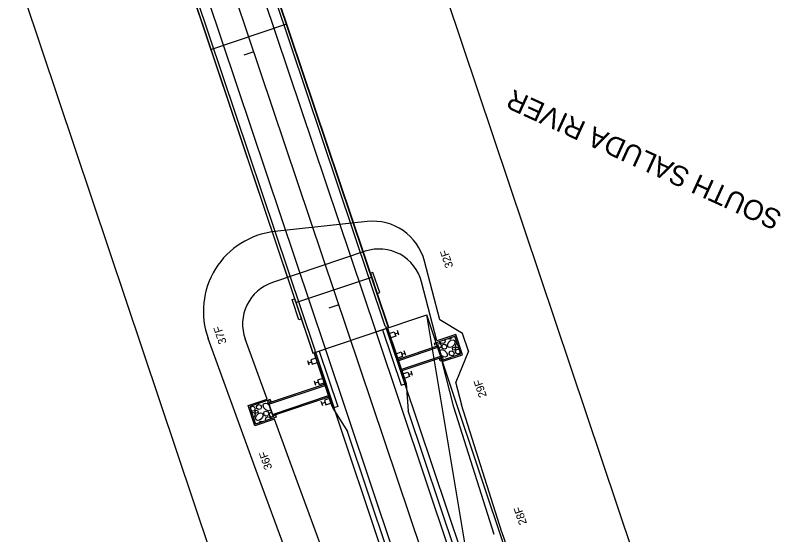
# Model space of a CAD drawing. Extents: x 1528853 to 1624411, y 1119753 to 1162242.
# Drawn here: x 1529554.1 to 1529845.6, y 1160111 to 1160305.3 of the extents above; entities that cross this region are included whole.
import ezdxf

# ---------------------------------------------------------------- set-up
doc = ezdxf.new("R2010")
doc.units = 0
for name, color, linetype in [('BR_CONCRETE', 7, 'Continuous'), ('BR_PROPOSED_TRAVELWAY', 7, 'Continuous'), ('Drainage-Trench', 7, 'Continuous'), ('RD_HC_Cl', 7, 'Continuous'), ('RD_HC_Data', 7, 'Continuous'), ('RD_HC_Data_Tic', 7, 'Continuous'), ('RD_PD_BOC', 7, 'Continuous'), ('RD_PD_CstnLmt', 7, 'Continuous'), ('RD_PD_CstnLmt_TX', 7, 'Continuous'), ('RD_PD_DR_ErosCtrl', 7, 'Continuous'), ('RD_PD_DR_Inlet', 7, 'Continuous'), ('RD_PD_Final_TrvlWay', 7, 'Continuous'), ('RD_PD_GR', 7, 'Continuous'), ('RD_PD_PaveDit', 7, 'Continuous'), ('RD_PD_PaveShd', 7, 'Continuous'), ('RD_PD_RW', 7, 'Continuous'), ('RD_Sketch8', 7, 'Continuous')]:
    doc.layers.add(name, color=color, linetype=linetype)

# ---------------------------------------------------------------- blocks, each defined once
blk = doc.blocks.new('Guardrail_MTBBC2_Transition')
at = {"layer": 'RD_PD_GR'}
for p, q in [((3.875, 3.75), (2.125, 3.75)), ((3, 2.5), (3, 3.75)), ((11.875, 3.75), (10.125, 3.75)), ((11, 2.5), (11, 3.75)), ((19.875, 3.75), (18.125, 3.75)), ((19, 2.5), (19, 3.75)), ((0, 0.5), (0, 0)), ((21.25, 0.5), (0, 0.5)), ((0, 0), (21.25, 0)), ((2.125, 0.5), (2.125, 2.5)), ((2.125, 2.5), (3.875, 2.5)), ((3.875, 0.5), (2.125, 0.5)), ((3.875, 2.5), (3.875, 0.5)), ((10.125, 0.5), (10.125, 2.5)), ((10.125, 2.5), (11.875, 2.5)), ((11.875, 0.5), (10.125, 0.5)), ((11.875, 2.5), (11.875, 0.5)), ((15, 0.5), (15, 0)), ((18.125, 0.5), (18.125, 2.5)), ((18.125, 2.5), (19.875, 2.5)), ((19.875, 0.5), (18.125, 0.5)), ((19.875, 2.5), (19.875, 0.5)), ((21.25, 0), (21.25, 0.5))]:
    blk.add_line(p, q, dxfattribs=at)

msp = doc.modelspace()

# ---------------------------------------------------------------- linework, layer by layer
at = {"layer": 'BR_CONCRETE'}
for p, q in [((1529692.58, 1160189.08), (1529632.72, 1160367.29)), ((1529693.85, 1160188.45), (1529633.35, 1160368.56)), ((1529693.93, 1160188.48), (1529633.43, 1160368.58)), ((1529604.99, 1160359.03), (1529665.49, 1160178.92)), ((1529665.57, 1160178.95), (1529605.07, 1160359.06)), ((1529666.2, 1160180.22), (1529606.34, 1160358.43)), ((1529627.28, 1160292.68), (1529655.72, 1160302.23)), ((1529659.12, 1160197.88), (1529687.56, 1160207.43)), ((1529692.58, 1160189.08), (1529693.14, 1160188.21)), ((1529665.49, 1160178.92), (1529693.93, 1160188.48)), ((1529666.2, 1160180.22), (1529666.28, 1160179.19))]:
    msp.add_line(p, q, dxfattribs=at)
for points in [[(1529688.03, 1160209.17), (1529687.08, 1160208.86), (1529689.63, 1160201.27), (1529690.58, 1160201.59)], [(1529657.7, 1160198.98), (1529658.65, 1160199.3), (1529661.19, 1160191.72), (1529660.24, 1160191.4)]]:
    msp.add_lwpolyline(points, close=True, dxfattribs=at)
at = {"layer": 'BR_PROPOSED_TRAVELWAY'}
for p, q in [((1529689.19, 1160186.88), (1529628.69, 1160366.99)), ((1529670.23, 1160180.51), (1529609.73, 1160360.62))]:
    msp.add_line(p, q, dxfattribs=at)
at = {"layer": 'Drainage-Trench'}
for p, q in [((1529711.03, 1160182.71), (1529718.73, 1160185.29)), ((1529720.96, 1160178.66), (1529718.73, 1160185.29)), ((1529711.35, 1160181.76), (1529711.03, 1160182.71)), ((1529713.89, 1160177.34), (1529712.3, 1160182.08)), ((1529713.26, 1160176.07), (1529720.96, 1160178.66)), ((1529713.26, 1160176.07), (1529712.94, 1160177.02)), ((1529649.54, 1160161.52), (1529641.84, 1160158.93)), ((1529648.91, 1160160.25), (1529650.5, 1160155.51)), ((1529649.54, 1160161.52), (1529649.85, 1160160.57)), ((1529641.84, 1160158.93), (1529644.07, 1160152.3)), ((1529651.76, 1160154.88), (1529644.07, 1160152.3)), ((1529651.45, 1160155.83), (1529651.76, 1160154.88))]:
    msp.add_line(p, q, dxfattribs=at)
at = {"layer": 'RD_HC_Cl'}
msp.add_line((1529913.5, 1159487.74), (1529500.12, 1160718.34), dxfattribs=at)
at = {"layer": 'RD_HC_Data_Tic'}
for p, q in [((1529643.41, 1160291.76), (1529639.62, 1160290.49)), ((1529675.25, 1160196.97), (1529671.46, 1160195.7))]:
    msp.add_line(p, q, dxfattribs=at)
at = {"layer": 'RD_PD_BOC'}
for p, q in [((1529691.56, 1160187.68), (1529698.54, 1160166.9)), ((1529693.46, 1160188.32), (1529700.43, 1160167.54)), ((1529665.97, 1160179.08), (1529672.94, 1160158.31)), ((1529667.86, 1160179.72), (1529674.84, 1160158.94)), ((1529698.54, 1160166.9), (1529700.43, 1160167.54)), ((1529674.84, 1160158.94), (1529672.94, 1160158.31))]:
    msp.add_line(p, q, dxfattribs=at)
at = {"layer": 'RD_PD_CstnLmt'}
for p, q in [((1529685.13, 1160217.06), (1529650.36, 1160205.38)), ((1529711.96, 1160183.54), (1529706.23, 1160205.63)), ((1529719.05, 1160185.92), (1529711.96, 1160183.54)), ((1529721.59, 1160178.34), (1529719.05, 1160185.92)), ((1529648.38, 1160161.66), (1529640.17, 1160184.23)), ((1529713.97, 1160175.78), (1529721.59, 1160178.34)), ((1529718.39, 1160158.72), (1529713.97, 1160175.78)), ((1529641.21, 1160159.25), (1529648.38, 1160161.66)), ((1529643.75, 1160151.67), (1529641.21, 1160159.25)), ((1529733.43, 1160111.02), (1529718.39, 1160158.72)), ((1529651.12, 1160154.14), (1529643.75, 1160151.67)), ((1529656.96, 1160138.08), (1529651.12, 1160154.14)), ((1529674.28, 1160091.15), (1529656.96, 1160138.08))]:
    msp.add_line(p, q, dxfattribs=at)
for centre, start, end in [((1529690.36, 1160201.52), 14.533, 108.568), ((1529655.58, 1160189.83), 108.568, 199.9899)]:
    msp.add_arc(centre, 16.4, start, end, dxfattribs=at)
at = {"layer": 'RD_PD_DR_ErosCtrl'}
for p, q in [((1529685.8, 1160228.21), (1529651.23, 1160224.44)), ((1529713.03, 1160191.34), (1529707.33, 1160213.35)), ((1529721.58, 1160186.25), (1529713.03, 1160191.34)), ((1529723.8, 1160179.61), (1529721.58, 1160186.25)), ((1529644.75, 1160133.61), (1529626.29, 1160184.36)), ((1529723.8, 1160179.61), (1529719.09, 1160167.99)), ((1529721.3, 1160159.47), (1529719.09, 1160167.99)), ((1529736.3, 1160111.92), (1529721.25, 1160159.62)), ((1529661.93, 1160087.08), (1529644.75, 1160133.61)), ((1529753.24, 1160065), (1529736.28, 1160111.98))]:
    msp.add_line(p, q, dxfattribs=at)
for centre, radius, start, end in [((1529687.97, 1160208.33), 20, 14.533, 96.2338), ((1529654.48, 1160194.61), 30, 96.2338, 199.9899)]:
    msp.add_arc(centre, radius, start, end, dxfattribs=at)
at = {"layer": 'RD_PD_DR_Inlet'}
for p, q in [((1529712.46, 1160181.6), (1529697.41, 1160176.55)), ((1529712.62, 1160181.13), (1529697.57, 1160176.07)), ((1529712.46, 1160181.6), (1529713.89, 1160177.34)), ((1529713.73, 1160177.81), (1529698.68, 1160172.75)), ((1529713.89, 1160177.34), (1529698.84, 1160172.28)), ((1529648.91, 1160160.25), (1529669.92, 1160167.31)), ((1529649.07, 1160159.78), (1529670.08, 1160166.84)), ((1529650.34, 1160155.99), (1529671.35, 1160163.05)), ((1529650.5, 1160155.51), (1529671.51, 1160162.57)), ((1529650.5, 1160155.51), (1529648.91, 1160160.25))]:
    msp.add_line(p, q, dxfattribs=at)
at = {"layer": 'RD_PD_Final_TrvlWay'}
for p, q in [((1529922.97, 1159490.92), (1529689.19, 1160186.88)), ((1529904.02, 1159484.55), (1529670.23, 1160180.51))]:
    msp.add_line(p, q, dxfattribs=at)
at = {"layer": 'RD_PD_GR'}
for p, q in [((1529699.75, 1160168.01), (1529727.61, 1160085.07)), ((1529734.82, 1159975.67), (1529673.21, 1160159.1))]:
    msp.add_line(p, q, dxfattribs=at)
at = {"layer": 'RD_PD_PaveDit'}
for p, q in [((1529712.95, 1160182.99), (1529712.72, 1160183.27)), ((1529716.84, 1160184.17), (1529716.08, 1160184.4)), ((1529712.82, 1160180.69), (1529712.76, 1160180.71)), ((1529713.86, 1160177.89), (1529713.6, 1160178.2)), ((1529648.94, 1160159.7), (1529649.2, 1160159.39)), ((1529649.97, 1160156.89), (1529650.04, 1160156.88)), ((1529649.85, 1160154.6), (1529650.08, 1160154.32)), ((1529645.96, 1160153.42), (1529646.72, 1160153.19))]:
    msp.add_line(p, q, dxfattribs=at)
for points in [[(1529714.82, 1160183.98), (1529715.03, 1160183.38), (1529714.85, 1160182.78), (1529714.18, 1160182.5), (1529713.43, 1160182.69), (1529712.92, 1160183.02)], [(1529716.46, 1160183.09), (1529717.23, 1160183.74), (1529718.08, 1160183.95), (1529718.59, 1160183.71), (1529718.8, 1160183.03), (1529718.46, 1160182.08), (1529717.7, 1160181.31), (1529716.84, 1160181.01), (1529716.24, 1160181.19), (1529715.97, 1160181.86), (1529716.15, 1160182.61), (1529716.48, 1160183.12)], [(1529717.6, 1160184.91), (1529717.4, 1160184.49), (1529716.84, 1160184.17)], [(1529718.92, 1160184.72), (1529718.72, 1160184.96), (1529718.65, 1160185.26)], [(1529711.79, 1160181.91), (1529712.06, 1160182.41), (1529712.85, 1160182.59), (1529713.4, 1160182.25), (1529713.6, 1160181.48), (1529713.38, 1160181.01), (1529712.82, 1160180.69)], [(1529713.1, 1160179.71), (1529713.24, 1160180.03), (1529713.91, 1160180.24), (1529714.87, 1160179.9), (1529715.64, 1160179.14), (1529715.94, 1160178.28), (1529715.76, 1160177.68), (1529715.09, 1160177.4), (1529714.34, 1160177.59), (1529713.83, 1160177.92)], [(1529714.93, 1160180.4), (1529714.08, 1160180.65), (1529713.78, 1160181.4), (1529714.16, 1160182.11), (1529714.95, 1160182.29), (1529715.5, 1160181.95), (1529715.7, 1160181.18), (1529715.48, 1160180.71), (1529714.93, 1160180.4)], [(1529718.5, 1160180.02), (1529718, 1160180.17), (1529717.82, 1160180.62), (1529718.04, 1160181.05), (1529718.52, 1160181.15), (1529718.85, 1160180.95), (1529718.97, 1160180.49), (1529718.83, 1160180.21), (1529718.5, 1160180.02)], [(1529720.06, 1160180.81), (1529719.22, 1160181.06), (1529718.92, 1160181.81), (1529719.29, 1160182.53), (1529719.63, 1160182.6)], [(1529720.07, 1160178.57), (1529719.23, 1160178.82), (1529718.93, 1160179.56), (1529719.3, 1160180.28), (1529720.09, 1160180.46), (1529720.42, 1160180.26)], [(1529720.21, 1160180.9), (1529720.06, 1160180.81)], [(1529713.76, 1160176.48), (1529713.25, 1160176.63), (1529713.08, 1160177.06)], [(1529713.81, 1160177.59), (1529714.1, 1160177.41), (1529714.22, 1160176.95), (1529714.09, 1160176.67), (1529713.75, 1160176.48)], [(1529717.66, 1160177.91), (1529716.82, 1160178.16), (1529716.52, 1160178.91), (1529716.89, 1160179.62), (1529717.69, 1160179.8), (1529718.24, 1160179.46), (1529718.44, 1160178.69), (1529718.21, 1160178.22), (1529717.66, 1160177.91)], [(1529720.77, 1160179.21), (1529720.62, 1160178.88), (1529720.07, 1160178.57)], [(1529645.14, 1160159.68), (1529645.98, 1160159.43), (1529646.28, 1160158.68), (1529645.91, 1160157.97), (1529645.11, 1160157.79), (1529644.56, 1160158.13), (1529644.36, 1160158.9), (1529644.59, 1160159.37), (1529645.14, 1160159.68)], [(1529649.7, 1160157.88), (1529649.56, 1160157.56), (1529648.89, 1160157.35), (1529647.93, 1160157.69), (1529647.16, 1160158.45), (1529646.86, 1160159.31), (1529647.04, 1160159.91), (1529647.71, 1160160.19), (1529648.46, 1160160), (1529648.97, 1160159.67)], [(1529648.99, 1160160), (1529648.7, 1160160.18), (1529648.58, 1160160.64), (1529648.71, 1160160.92), (1529649.04, 1160161.11)], [(1529649.04, 1160161.11), (1529649.55, 1160160.96), (1529649.72, 1160160.53)], [(1529642.02, 1160158.38), (1529642.18, 1160158.71), (1529642.73, 1160159.02)], [(1529642.73, 1160159.02), (1529643.57, 1160158.77), (1529643.87, 1160158.02), (1529643.5, 1160157.31), (1529642.7, 1160157.13), (1529642.38, 1160157.33)], [(1529642.59, 1160156.69), (1529642.74, 1160156.78)], [(1529642.74, 1160156.78), (1529643.58, 1160156.53), (1529643.88, 1160155.78), (1529643.5, 1160155.06), (1529643.17, 1160154.99)], [(1529644.3, 1160157.57), (1529644.8, 1160157.42), (1529644.98, 1160156.97), (1529644.76, 1160156.54), (1529644.28, 1160156.43), (1529643.95, 1160156.64), (1529643.83, 1160157.1), (1529643.97, 1160157.38), (1529644.3, 1160157.57)], [(1529647.87, 1160157.19), (1529648.71, 1160156.94), (1529649.01, 1160156.19), (1529648.64, 1160155.48), (1529647.85, 1160155.29), (1529647.3, 1160155.63), (1529647.1, 1160156.41), (1529647.32, 1160156.88), (1529647.87, 1160157.19)], [(1529651, 1160155.68), (1529650.74, 1160155.18), (1529649.95, 1160155), (1529649.4, 1160155.34), (1529649.2, 1160156.11), (1529649.42, 1160156.58), (1529649.97, 1160156.89)], [(1529646.34, 1160154.5), (1529645.57, 1160153.85), (1529644.72, 1160153.64), (1529644.21, 1160153.88), (1529644, 1160154.55), (1529644.33, 1160155.51), (1529645.1, 1160156.28), (1529645.95, 1160156.58), (1529646.56, 1160156.4), (1529646.83, 1160155.73), (1529646.65, 1160154.98), (1529646.32, 1160154.47)], [(1529647.98, 1160153.61), (1529647.77, 1160154.21), (1529647.95, 1160154.81), (1529648.62, 1160155.09), (1529649.37, 1160154.9), (1529649.88, 1160154.57)], [(1529643.88, 1160152.87), (1529644.08, 1160152.63), (1529644.15, 1160152.33)], [(1529645.2, 1160152.68), (1529645.4, 1160153.1), (1529645.96, 1160153.42)]]:
    msp.add_lwpolyline(points, dxfattribs=at)
at = {"layer": 'RD_PD_PaveShd'}
for p, q in [((1529700.43, 1160167.54), (1529701.25, 1160157.28)), ((1529672.94, 1160158.31), (1529678.5, 1160149.61)), ((1529754.8, 1159997.85), (1529701.25, 1160157.28)), ((1529732.05, 1159990.21), (1529678.5, 1160149.61))]:
    msp.add_line(p, q, dxfattribs=at)
at = {"layer": 'RD_PD_RW'}
for p, q in [((1529881.68, 1159817.98), (1529571.21, 1160742.22)), ((1529715.61, 1159841.31), (1529429.02, 1160694.46))]:
    msp.add_line(p, q, dxfattribs=at)
at = {"layer": 'RD_Sketch8'}
for p in [(1529689.19, 1160186.88), (1529747.95, 1160074.76), (1529728.99, 1160068.39)]:
    msp.add_line(p, (1529708.15, 1160193.25), dxfattribs=at)

# ---------------------------------------------------------------- block references
at = {"layer": 'RD_PD_BOC', "rotation": -71.4319942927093}
msp.add_blockref('Guardrail_MTBBC2_Transition', (1529692.98, 1160188.16), dxfattribs=at)
at = {"layer": 'RD_PD_BOC', "yscale": -0.9999999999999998, "rotation": -71.43199429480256}
msp.add_blockref('Guardrail_MTBBC2_Transition', (1529666.44, 1160179.24), dxfattribs=at)

# ---------------------------------------------------------------- texts
at = {"layer": 'RD_HC_Data'}
msp.add_text('SOUTH SALUDA RIVER', height=7.5, rotation=155.4399, dxfattribs=at).set_placement((1529841.77, 1160231.58))
at = {"layer": 'RD_PD_CstnLmt_TX'}
for s, p in [('32F', (1529718.14, 1160211.38)), ('37F', (1529633.23, 1160182.85)), ('29F', (1529730.72, 1160162.86)), ('36F', (1529650.32, 1160135.85)), ('28F', (1529745.76, 1160115.16))]:
    msp.add_text(s, height=3, rotation=108.568, dxfattribs=at).set_placement(p)

doc.saveas('drawing.dxf')
